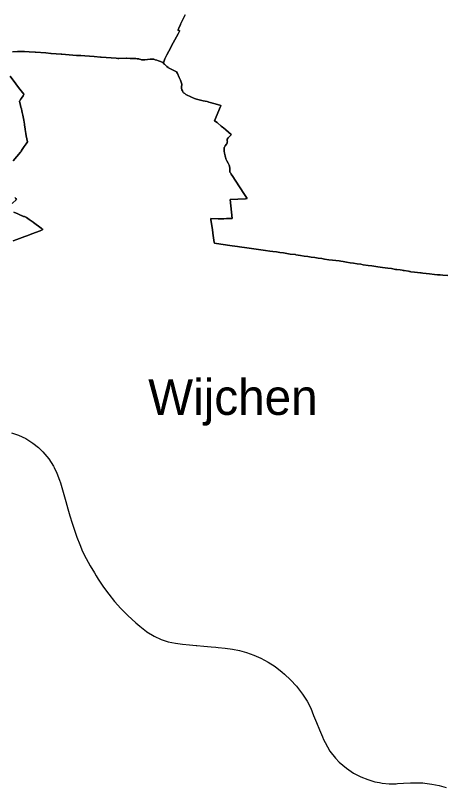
# Model space of a CAD drawing. Extents: x 113371 to 291721, y 393993 to 520143.
# Drawn here: x 172256 to 178291, y 420688 to 431522 of the extents above; entities that cross this region are included whole.
import ezdxf

# ---------------------------------------------------------------- set-up
doc = ezdxf.new("R2010")
doc.units = 0
doc.layers.add('Gemeentegrenzen', color=7, linetype='Continuous')
doc.layers.add('Woonplaatsnamen', color=7, linetype='Continuous')

msp = doc.modelspace()

# ---------------------------------------------------------------- linework, layer by layer
at = {"layer": 'Gemeentegrenzen'}
for points in [[(172212.046, 431012.313), (172282.559, 431017.477), (172291.386, 431017.983), (172297.595, 431018.005), (172298.16, 431018.007), (172300.26, 431017.984), (172300.677, 431017.996), (172303.45, 431018.08), (172336.36, 431018.622), (172358.915, 431017.536), (172383.703, 431016.037), (172449.393, 431012.941), (172531.986, 431007.882), (172534.91, 431007.451), (172538.847, 431007.273), (172683.485, 430995.712), (172751.144, 430990.188), (172757.182, 430990.696), (172899.137, 430978.673), (172905.544, 430978.09), (173110.752, 430962.213), (173165.711, 430958.437), (173174.61, 430958.272), (173227.996, 430954.422), (173296.986, 430949.846), (173360.462, 430944.955), (173448.237, 430938.471), (173456.611, 430938.239), (173597.85, 430927.824), (173667.262, 430923.003), (173669.402, 430922.158), (173690.519, 430919.437), (173706.055, 430919.047), (173807.034, 430920.71), (173814.961, 430920.61), (173865.477, 430919.97), (173898.533, 430918.321), (173924.078, 430916.62), (173943.605, 430916.194), (173962.928, 430914.389), (173986.051, 430913.04), (173996.561, 430910.627), (174015.29, 430904.078), (174023.413, 430901.065), (174040.606, 430899.188), (174049.18, 430898.646), (174065.015, 430899.943), (174072.936, 430901.142), (174146.691, 430908.706), (174158.906, 430909.555), (174170.849, 430909.007), (174185.243, 430907.478), (174196.185, 430906.805), (174218.237, 430901.4), (174238.28, 430895.676), (174263.506, 430886.319), (174290.919, 430874.696), (174323.06, 430859.775), (174330.39, 430856.505), (174336.318, 430872.117), (174345.306, 430897.959), (174353.594, 430915.435), (174364.822, 430941.303), (174381.056, 430971.171), (174408.854, 431020.745), (174436.665, 431074.004), (174442.856, 431085.96), (174470.511, 431137.09), (174539.458, 431264.857), (174549.957, 431285.129), (174558.371, 431301.907), (174560.029, 431305.489), (174559.564, 431307.389), (174558.61, 431308.989), (174558.015, 431309.491), (174556.655, 431310.638), (174553.672, 431311.745), (174546.342, 431314.007), (174533.532, 431317.556), (174546.022, 431344.656), (174547.667, 431348.196), (174569.839, 431392.301), (174572.641, 431397.874), (174587.276, 431426.987), (174638.75, 431529.379)], [(174638.75, 431529.379), (174587.276, 431426.987), (174572.641, 431397.874), (174569.839, 431392.301), (174547.667, 431348.196), (174546.022, 431344.656), (174533.532, 431317.556), (174546.342, 431314.007), (174553.672, 431311.745), (174556.655, 431310.638), (174558.015, 431309.491), (174558.61, 431308.989), (174559.564, 431307.389), (174560.029, 431305.489), (174558.371, 431301.907), (174549.957, 431285.129), (174539.458, 431264.857), (174470.511, 431137.09), (174442.856, 431085.96), (174436.665, 431074.004), (174408.854, 431020.745), (174381.056, 430971.171), (174364.822, 430941.303), (174353.594, 430915.435), (174345.306, 430897.959), (174336.318, 430872.117), (174330.39, 430856.505), (174330.032, 430851.586), (174334.344, 430849.544), (174345.78, 430839.846), (174357.159, 430827.935), (174374.784, 430808.884), (174377.733, 430806.157), (174398.193, 430791.687), (174402.72, 430789.14), (174514.605, 430729.032), (174531.734, 430705.626), (174553.855, 430653.779), (174570.599, 430614.457), (174581.119, 430588.22), (174589.139, 430560.221), (174588.895, 430544.334), (174587.616, 430531.863), (174586.646, 430519.493), (174586.142, 430499.887), (174592.702, 430478.073), (174597.785, 430465.01), (174602.749, 430452.875), (174604.604, 430449.226), (174611.494, 430440.568), (174613.452, 430438.553), (174630.447, 430425.75), (174639.65, 430419.22), (174647.037, 430414.733), (174664.467, 430404.989), (174676.305, 430398.673), (174697.264, 430389.022), (174725.039, 430376.332), (174769.487, 430356.258), (174794.118, 430349.321), (174891.616, 430325.65), (174943.675, 430313.159), (174960.422, 430309.03), (174969.812, 430306.571), (175055.938, 430281.797), (175139.939, 430258.784), (175138.334, 430254.812), (175133.07, 430244.17), (175050.363, 430041.326), (175084.11, 430019.26), (175089.96, 430015.06), (175142.22, 429969.82), (175160.91, 429954.55), (175174.53, 429943.51), (175206.48, 429918.4), (175283.826, 429853.978), (175285.694, 429852.403), (175269.143, 429833.186), (175254.732, 429816.939), (175242.879, 429804.3), (175224.541, 429786.396), (175227.815, 429765.908), (175228.836, 429758.674), (175229.054, 429751.412), (175228.796, 429744.819), (175228.159, 429739.795), (175227.147, 429736.159), (175220.452, 429723.137), (175215.05, 429713.81), (175200.17, 429690.893), (175188.688, 429673.159), (175186.363, 429669.642), (175184.849, 429664.759), (175183.451, 429657.146), (175182.523, 429645.853), (175183.735, 429623.528), (175185.105, 429615.708), (175190.397, 429591.368), (175199.697, 429550.45), (175204.217, 429529.321), (175206.776, 429518.565), (175209.028, 429511.928), (175212.993, 429500.631), (175217.583, 429489.838), (175223.269, 429480.091), (175239.401, 429449.876), (175249.084, 429431.226), (175252.737, 429423.389), (175255.609, 429415.932), (175257.67, 429409.841), (175259.768, 429402.216), (175261.503, 429394.402), (175262.46, 429387.632), (175262.922, 429377.558), (175262.959, 429375.206), (175263.285, 429354.572), (175264.121, 429336.917), (175264.444, 429331.881), (175266.242, 429324.728), (175270.14, 429317.458), (175277.215, 429307.818), (175284.23, 429297.005), (175305.162, 429262.808), (175338.817, 429211.068), (175469.441, 429009.637), (175506.893, 428953.602), (175504.682, 428953.195), (175485.781, 428950.813), (175268.3, 428941.138), (175295.359, 428672.265), (175218.64, 428670.827), (175177.828, 428670.437), (175167.09, 428670.14), (175155.375, 428670.628), (175101.489, 428670.557), (174997.02, 428670.877), (174997.468, 428664.277), (174997.955, 428657.09), (174998.694, 428652.379), (175019.669, 428518.609), (175026.058, 428469.567), (175045.364, 428336.669), (175047.071, 428324.921), (175135.855, 428312.074), (175296.937, 428288.797), (175370.668, 428278.348), (175400.55, 428274.113), (175500.353, 428260.046), (175762.447, 428224.118), (175825.83, 428216.979), (175866.92, 428210.694), (175916.911, 428204.247), (175966.32, 428197.088), (176015.409, 428189.711), (176065.117, 428181.515), (176110.407, 428174.525), (176185.36, 428165.992), (176188.529, 428165.552), (176257.466, 428153.465), (176307.267, 428146.197), (176356.69, 428139.143), (176406.374, 428131.79), (176456.07, 428124.181), (176505.411, 428116.933), (176555.008, 428110.006), (176591.997, 428104.625), (176653.859, 428095.28), (176703.524, 428089.113), (176753.413, 428083.066), (176796.916, 428077.598), (176822.371, 428074.058), (176851.997, 428069.253), (176901.701, 428060.717), (176950.747, 428052.899), (177000.202, 428045.069), (177050.215, 428037.511), (177099.938, 428031.387), (177134.413, 428025.059), (177204.909, 428013.398), (177206.335, 428015.284), (177254.496, 428008.374), (177339.742, 427996.376), (177405.88, 427987.087), (177479.78, 427976.49), (177531.282, 427969.576), (177588.029, 427959.74), (177609.622, 427955.823), (177653.646, 427951.714), (177683.119, 427946.266), (177696.76, 427944.098), (177703.933, 427941.649), (177708.995, 427943.124), (177771.965, 427932.727), (177785.492, 427930.58), (177795.366, 427928.146), (177804.191, 427926.647), (177857.385, 427920.37), (177937.998, 427909.825), (177941.779, 427909.924), (177946.809, 427909.964), (177950.171, 427909.831), (177971.625, 427906.452), (178067.252, 427895.373), (178136.525, 427888.489), (178179.006, 427884.185), (178214.766, 427881.191), (178250.927, 427879.429), (178323.251, 427871.131)], [(178323.251, 427871.131), (178250.927, 427879.429), (178214.766, 427881.191), (178179.006, 427884.185), (178136.525, 427888.489), (178067.252, 427895.373), (177971.625, 427906.452), (177950.171, 427909.831), (177946.809, 427909.964), (177941.779, 427909.924), (177937.998, 427909.825), (177857.385, 427920.37), (177804.191, 427926.647), (177795.366, 427928.146), (177785.492, 427930.58), (177771.965, 427932.727), (177708.995, 427943.124), (177703.933, 427941.649), (177696.76, 427944.098), (177683.119, 427946.266), (177653.646, 427951.714), (177609.622, 427955.823), (177588.029, 427959.74), (177531.282, 427969.576), (177479.78, 427976.49), (177405.88, 427987.087), (177339.742, 427996.376), (177254.496, 428008.374), (177206.335, 428015.284), (177204.909, 428013.398), (177134.413, 428025.059), (177099.938, 428031.387), (177050.215, 428037.511), (177000.202, 428045.069), (176950.747, 428052.899), (176901.701, 428060.717), (176851.997, 428069.253), (176822.371, 428074.058), (176796.916, 428077.598), (176753.413, 428083.066), (176703.524, 428089.113), (176653.859, 428095.28), (176591.997, 428104.625), (176555.008, 428110.006), (176505.411, 428116.933), (176456.07, 428124.181), (176406.374, 428131.79), (176356.69, 428139.143), (176307.267, 428146.197), (176257.466, 428153.465), (176188.529, 428165.552), (176185.36, 428165.992), (176110.407, 428174.525), (176065.117, 428181.515), (176015.409, 428189.711), (175966.32, 428197.088), (175916.911, 428204.247), (175866.92, 428210.694), (175825.83, 428216.979), (175762.447, 428224.118), (175500.353, 428260.046), (175400.55, 428274.113), (175370.668, 428278.348), (175296.937, 428288.797), (175135.855, 428312.074), (175047.071, 428324.921), (175045.364, 428336.669), (175026.058, 428469.567), (175019.669, 428518.609), (174998.694, 428652.379), (174997.955, 428657.09), (174997.468, 428664.277), (174997.02, 428670.877), (175101.489, 428670.557), (175155.375, 428670.628), (175167.09, 428670.14), (175177.828, 428670.437), (175218.64, 428670.827), (175295.359, 428672.265), (175268.3, 428941.138), (175485.781, 428950.813), (175504.682, 428953.195), (175506.893, 428953.602), (175469.441, 429009.637), (175338.817, 429211.068), (175305.162, 429262.808), (175284.23, 429297.005), (175277.215, 429307.818), (175270.14, 429317.458), (175266.242, 429324.728), (175264.444, 429331.881), (175264.121, 429336.917), (175263.285, 429354.572), (175262.959, 429375.206), (175262.922, 429377.558), (175262.46, 429387.632), (175261.503, 429394.402), (175259.768, 429402.216), (175257.67, 429409.841), (175255.609, 429415.932), (175252.737, 429423.389), (175249.084, 429431.226), (175239.401, 429449.876), (175223.269, 429480.091), (175217.583, 429489.838), (175212.993, 429500.631), (175209.028, 429511.928), (175206.776, 429518.565), (175204.217, 429529.321), (175199.697, 429550.45), (175190.397, 429591.368), (175185.105, 429615.708), (175183.735, 429623.528), (175182.523, 429645.853), (175183.451, 429657.146), (175184.849, 429664.759), (175186.363, 429669.642), (175188.688, 429673.159), (175200.17, 429690.893), (175215.05, 429713.81), (175220.452, 429723.137), (175227.147, 429736.159), (175228.159, 429739.795), (175228.796, 429744.819), (175229.054, 429751.412), (175228.836, 429758.674), (175227.815, 429765.908), (175224.541, 429786.396), (175242.879, 429804.3), (175254.732, 429816.939), (175269.143, 429833.186), (175285.694, 429852.403), (175283.826, 429853.978), (175206.48, 429918.4), (175174.53, 429943.51), (175160.91, 429954.55), (175142.22, 429969.82), (175089.96, 430015.06), (175084.11, 430019.26), (175050.363, 430041.326), (175133.07, 430244.17), (175138.334, 430254.812), (175139.939, 430258.784), (175055.938, 430281.797), (174969.812, 430306.571), (174960.422, 430309.03), (174943.675, 430313.159), (174891.616, 430325.65), (174794.118, 430349.321), (174769.487, 430356.258), (174725.039, 430376.332), (174697.264, 430389.022), (174676.305, 430398.673), (174664.467, 430404.989), (174647.037, 430414.733), (174639.65, 430419.22), (174630.447, 430425.75), (174613.452, 430438.553), (174611.494, 430440.568), (174604.604, 430449.226), (174602.749, 430452.875), (174597.785, 430465.01), (174592.702, 430478.073), (174586.142, 430499.887), (174586.646, 430519.493), (174587.616, 430531.863), (174588.895, 430544.334), (174589.139, 430560.221), (174581.119, 430588.22), (174570.599, 430614.457), (174553.855, 430653.779), (174531.734, 430705.626), (174514.605, 430729.032), (174402.72, 430789.14), (174398.193, 430791.687), (174377.733, 430806.157), (174374.784, 430808.884), (174357.159, 430827.935), (174345.78, 430839.846), (174334.344, 430849.544), (174330.032, 430851.586), (174330.39, 430856.505), (174323.06, 430859.775), (174290.919, 430874.696), (174263.506, 430886.319), (174238.28, 430895.676), (174218.237, 430901.4), (174196.185, 430906.805), (174185.243, 430907.478), (174170.849, 430909.007), (174158.906, 430909.555), (174146.691, 430908.706), (174072.936, 430901.142), (174065.015, 430899.943), (174049.18, 430898.646), (174040.606, 430899.188), (174023.413, 430901.065), (174015.29, 430904.078), (173996.561, 430910.627), (173986.051, 430913.04), (173962.928, 430914.389), (173943.605, 430916.194), (173924.078, 430916.62), (173898.533, 430918.321), (173865.477, 430919.97), (173814.961, 430920.61), (173807.034, 430920.71), (173706.055, 430919.047), (173690.519, 430919.437), (173669.402, 430922.158), (173667.262, 430923.003), (173597.85, 430927.824), (173456.611, 430938.239), (173448.237, 430938.471), (173360.462, 430944.955), (173296.986, 430949.846), (173227.996, 430954.422), (173174.61, 430958.272), (173165.711, 430958.437), (173110.752, 430962.213), (172905.544, 430978.09), (172899.137, 430978.673), (172757.182, 430990.696), (172751.144, 430990.188), (172683.485, 430995.712), (172538.847, 431007.273), (172534.91, 431007.451), (172531.986, 431007.882), (172449.393, 431012.941), (172383.703, 431016.037), (172358.915, 431017.536), (172336.36, 431018.622), (172303.45, 431018.08), (172300.677, 431017.996), (172300.26, 431017.984), (172298.16, 431018.007), (172297.595, 431018.005), (172291.386, 431017.983), (172282.559, 431017.477), (172212.046, 431012.313)], [(172223.428, 429483.064), (172326.709, 429603.877), (172333.81, 429613.2), (172335.467, 429615.766), (172337.033, 429619.199), (172350.367, 429639.266), (172378.867, 429683.099), (172404.533, 429720.599), (172424.084, 429748.728), (172407.616, 429833.866), (172402.463, 429864.623), (172393.759, 429919.721), (172392.045, 429930.373), (172388.399, 429953.035), (172382.534, 429986.826), (172380.997, 429995.681), (172376.123, 430024.229), (172371.267, 430053.666), (172357.8, 430122.732), (172351.067, 430162.099), (172349.651, 430170.381), (172347.555, 430173.426), (172346.329, 430176.385), (172346.283, 430176.556), (172343.928, 430185.393), (172338.413, 430212.79), (172332.424, 430235.732), (172322.511, 430280.763), (172314.404, 430313.509), (172314.317, 430317.196), (172314.604, 430321.409), (172316.517, 430324.793), (172327.627, 430341.136), (172339.916, 430359.973), (172342.899, 430362.425), (172363.737, 430395.072), (172368.701, 430402.849), (172376.959, 430414.475), (172372.215, 430418.816), (172317.817, 430486.391), (172284.982, 430529.786), (172261.671, 430561.279), (172181.551, 430672.107)], [(172181.551, 430672.107), (172261.671, 430561.279), (172284.982, 430529.786), (172317.817, 430486.391), (172372.215, 430418.816), (172376.959, 430414.475), (172368.701, 430402.849), (172363.737, 430395.072), (172342.899, 430362.425), (172339.916, 430359.973), (172327.627, 430341.136), (172316.517, 430324.793), (172314.604, 430321.409), (172314.317, 430317.196), (172314.404, 430313.509), (172322.511, 430280.763), (172332.424, 430235.732), (172338.413, 430212.79), (172343.928, 430185.393), (172346.283, 430176.556), (172346.329, 430176.385), (172347.555, 430173.426), (172349.651, 430170.381), (172351.067, 430162.099), (172357.8, 430122.732), (172371.267, 430053.666), (172376.123, 430024.229), (172380.997, 429995.681), (172382.534, 429986.826), (172388.399, 429953.035), (172392.045, 429930.373), (172393.759, 429919.721), (172402.463, 429864.623), (172407.616, 429833.866), (172424.084, 429748.728), (172404.533, 429720.599), (172378.867, 429683.099), (172350.367, 429639.266), (172337.033, 429619.199), (172335.467, 429615.766), (172333.81, 429613.2), (172326.709, 429603.877), (172223.428, 429483.064)], [(172210.233, 428882.166), (172271.269, 428940.265), (172260.648, 428952.2), (172247.072, 428967.456)], [(172247.072, 428967.456), (172260.648, 428952.2), (172271.269, 428940.265), (172210.233, 428882.166)], [(172223.705, 428361.774), (172275.436, 428380.351), (172388.287, 428420.353), (172430.034, 428435.425), (172460.837, 428447.009), (172501.189, 428461.585), (172590.318, 428494.812), (172603.816, 428501.329), (172640.613, 428520.739), (172628.262, 428529.943), (172620.773, 428535.524), (172617.555, 428537.923), (172510.733, 428617.532), (172504.168, 428622.757), (172504.326, 428622.901), (172449.833, 428658.432), (172409.761, 428685.998), (172399.133, 428692.432), (172390.133, 428696.232), (172380.4, 428699.032), (172375.767, 428700.166), (172371.3, 428700.948), (172368.833, 428701.499), (172360.333, 428703.899), (172351.033, 428708.332), (172339.267, 428713.832), (172337.533, 428714.632), (172287.633, 428737.666), (172234.5, 428762.466)], [(172234.5, 428762.466), (172287.633, 428737.666), (172337.533, 428714.632), (172339.267, 428713.832), (172351.033, 428708.332), (172360.333, 428703.899), (172368.833, 428701.499), (172371.3, 428700.948), (172375.767, 428700.166), (172380.4, 428699.032), (172390.133, 428696.232), (172399.133, 428692.432), (172409.761, 428685.998), (172449.833, 428658.432), (172504.326, 428622.901), (172504.168, 428622.757), (172510.733, 428617.532), (172617.555, 428537.923), (172620.773, 428535.524), (172628.262, 428529.943), (172640.613, 428520.739), (172603.816, 428501.329), (172590.318, 428494.812), (172501.189, 428461.585), (172460.837, 428447.009), (172430.034, 428435.425), (172388.287, 428420.353), (172275.436, 428380.351), (172223.705, 428361.774)], [(172200, 425664), (172300, 425631), (172400, 425584), (172500, 425522), (172578, 425460), (172640, 425400), (172722, 425300), (172788, 425200), (172799.042, 425177.916), (172838, 425100), (172876, 425000), (172885.838, 424966.077), (172905, 424900), (172934, 424800), (172961, 424700), (172992, 424600), (173020, 424500), (173051, 424400), (173070.045, 424340.483), (173083, 424300), (173118, 424200), (173157, 424100), (173198, 424000), (173246, 423900), (173303, 423800), (173363, 423700), (173390.02, 423657.111), (173418.004, 423612.691), (173426, 423600), (173492, 423500), (173566, 423400), (173645, 423300), (173735, 423200), (173811.71, 423121.723), (173833, 423100), (173945, 423000), (174000, 422952), (174092.63, 422879.748), (174100, 422874), (174200, 422813), (174300, 422767), (174400, 422734), (174500, 422712), (174600, 422699), (174700, 422691), (174793.186, 422683.545), (174800, 422683), (174900, 422673), (175000, 422664), (175069.348, 422657.065), (175100, 422654), (175200, 422645), (175300, 422631), (175400, 422610), (175500, 422582), (175600, 422547), (175700, 422502), (175800, 422448), (175900, 422385), (176000, 422307), (176031.073, 422278.337), (176116, 422200), (176200, 422110), (176286, 422000), (176341.664, 421913.023), (176350, 421900), (176400, 421800), (176440, 421700), (176481, 421600), (176521, 421500), (176562, 421400), (176580.697, 421360.146), (176600, 421319), (176669, 421200), (176746, 421100), (176800, 421042), (176900, 420959), (177000, 420891), (177100, 420840), (177200, 420800), (177300, 420770), (177363.164, 420756.736), (177400, 420749), (177500, 420741), (177600, 420742), (177618.565, 420743.114), (177700, 420748), (177800, 420754), (177900, 420756), (177972.022, 420752.399), (178000, 420751), (178100, 420737), (178200, 420716), (178300, 420688)]]:
    msp.add_lwpolyline(points, dxfattribs=at)

# ---------------------------------------------------------------- texts
at = {"layer": 'Woonplaatsnamen'}
msp.add_text('Wijchen', height=500, dxfattribs=at).set_placement((174118.05, 425917.407))

doc.saveas('drawing.dxf')
